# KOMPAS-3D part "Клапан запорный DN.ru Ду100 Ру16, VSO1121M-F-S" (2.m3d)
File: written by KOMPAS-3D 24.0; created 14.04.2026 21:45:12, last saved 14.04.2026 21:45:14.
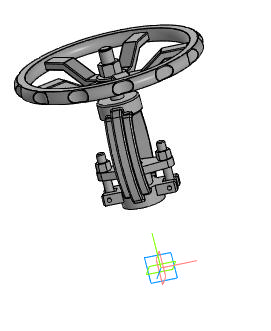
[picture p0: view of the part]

Document properties: Автор: R2D2; Полное имя файла: E:\Работа\Зайцев\VSO3131M-F-S Клапан запорный DN.ru Ду15-100 Ру40\DN100\исходные материалы\2.m3d

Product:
- Part/product: Клапан запорный DN.ru Ду100 Ру16  | designation VSO1121M-F-S
    Масса: 38.27
    Раздел спецификации: Прочие изделия
    Примечание: D090-01950

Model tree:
1. Операция без истории:1
2. Эскиз:1  (with: Ребро.Операция без истории:1)
3. Элемент вращения:1
     Угол 1 = 360
4. Эскиз:2  (with: Ребро.Операция без истории:1)
5. Элемент выдавливания:1
     Расстояние 1 = 54
6. Зеркальный массив:1
7. Экземпляр ( 1 )
8. Экземпляр ( 2 )  (with: Элемент выдавливания:1)

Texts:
  VSO1121M-F-S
